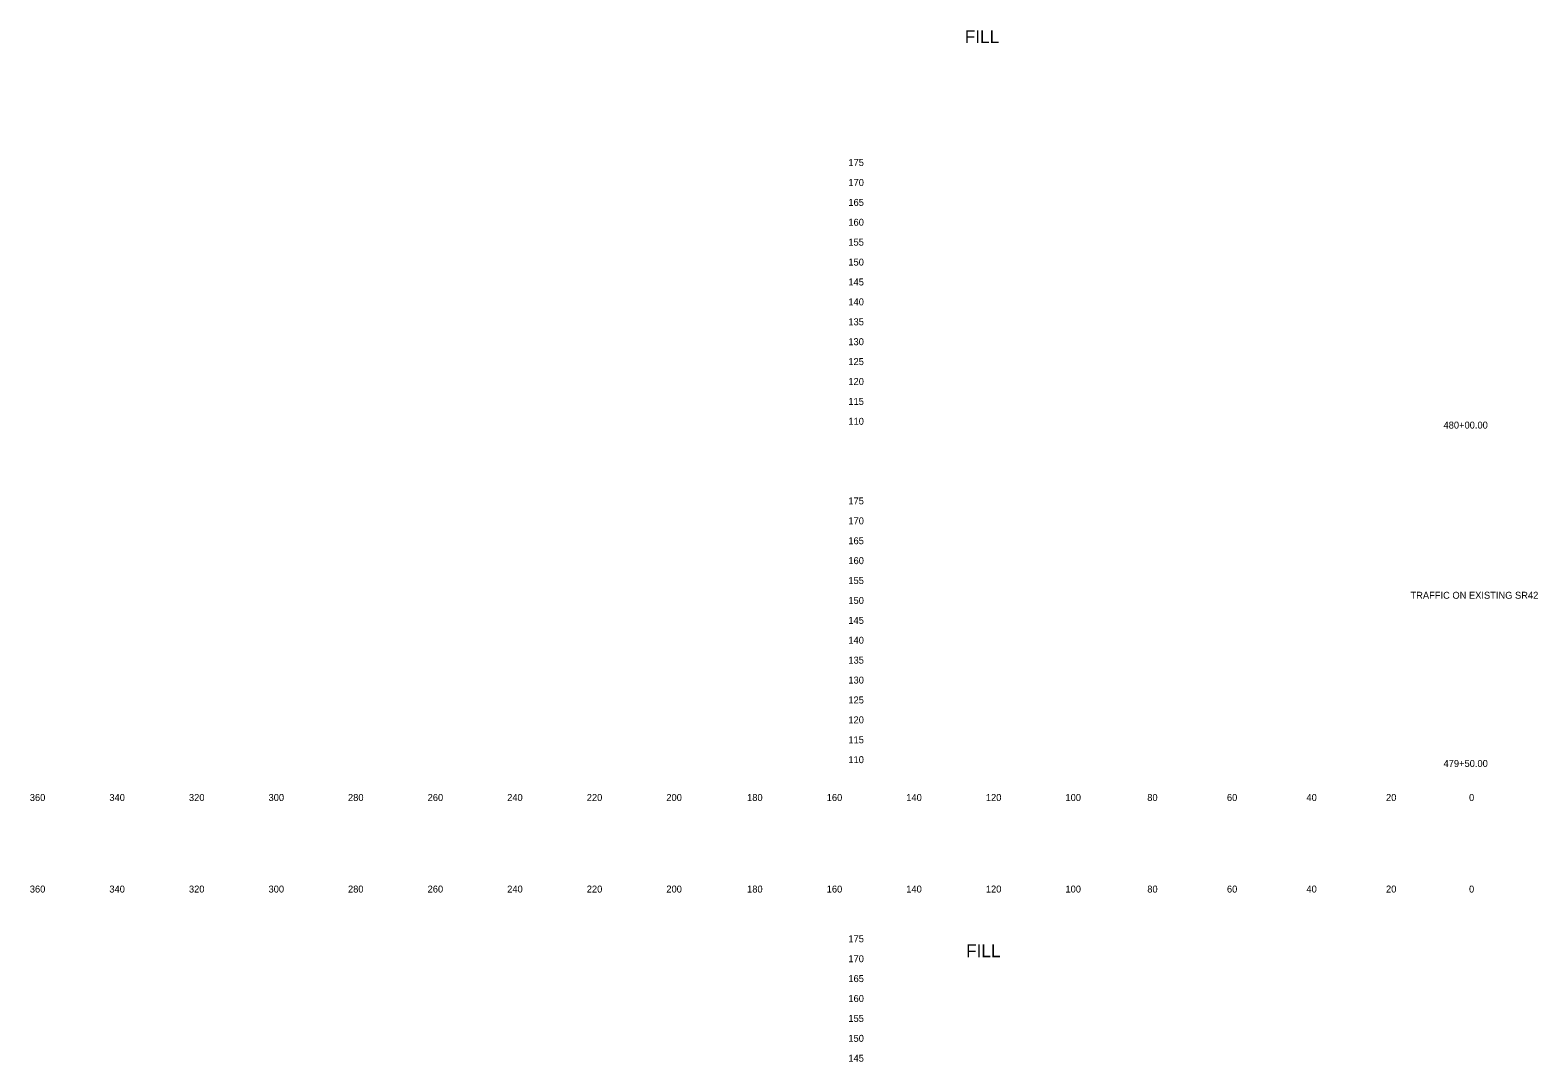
# Model space of a CAD drawing. Extents: x 21281 to 22024, y 6472 to 15198.
# Drawn here: x 21280.5 to 21659.4, y 11929.8 to 12189 of the extents above; entities that cross this region are included whole.
import ezdxf

# ---------------------------------------------------------------- set-up
doc = ezdxf.new("R2010")
doc.units = 0
for name, color, linetype in [('XS_SHEET_LABELS_ELEVATION', 7, 'Continuous'), ('XS_SHEET_LABELS_OFFSET', 7, 'Continuous'), ('XS_SHEET_LABELS_STATION', 7, 'Continuous')]:
    doc.layers.add(name, color=color, linetype=linetype)

msp = doc.modelspace()

# ---------------------------------------------------------------- texts
at = {"layer": 'XS_SHEET_LABELS_ELEVATION'}
for s, p in [('  175  ', (21484.84, 12154.84)), ('  170  ', (21484.84, 12149.84)), ('  165  ', (21484.84, 12144.84)), ('  160  ', (21484.84, 12139.84)), ('  155  ', (21484.84, 12134.84)), ('  150  ', (21484.84, 12129.84)), ('  145  ', (21484.84, 12124.84)), ('  140  ', (21484.84, 12119.84)), ('  135  ', (21484.84, 12114.84)), ('  130  ', (21484.84, 12109.84)), ('  125  ', (21484.84, 12104.84)), ('  120  ', (21484.84, 12099.84)), ('  115  ', (21484.84, 12094.84)), ('  110  ', (21484.84, 12089.84)), ('  175  ', (21484.84, 12069.84)), ('  170  ', (21484.84, 12064.84)), ('  165  ', (21484.84, 12059.84)), ('  160  ', (21484.84, 12054.84)), ('  155  ', (21484.84, 12049.84)), ('  150  ', (21484.84, 12044.84)), ('  145  ', (21484.84, 12039.84)), ('  140  ', (21484.84, 12034.84)), ('  135  ', (21484.84, 12029.84)), ('  130  ', (21484.84, 12024.84)), ('  125  ', (21484.84, 12019.84)), ('  120  ', (21484.84, 12014.84)), ('  115  ', (21484.84, 12009.84)), ('  110  ', (21484.84, 12004.84)), ('  175  ', (21484.84, 11959.84)), ('  170  ', (21484.84, 11954.84)), ('  165  ', (21484.84, 11949.84)), ('  160  ', (21484.84, 11944.84)), ('  155  ', (21484.84, 11939.84)), ('  150  ', (21484.84, 11934.84)), ('  145  ', (21484.84, 11929.84))]:
    msp.add_text(s, height=1.75, dxfattribs=at).set_placement(p)
at = {"layer": 'XS_SHEET_LABELS_OFFSET'}
for s, height, p in [('FILL', 3.222, (21515.4, 12185.75)), ('  360  ', 1.75, (21279.14, 11995.34)), ('  340  ', 1.75, (21299.13, 11995.34)), ('  320  ', 1.75, (21319.13, 11995.34)), ('  300  ', 1.75, (21339.13, 11995.34)), ('  280  ', 1.75, (21359.1, 11995.34)), ('  260  ', 1.75, (21379.11, 11995.34)), ('  240  ', 1.75, (21399.1, 11995.34)), ('  220  ', 1.75, (21419.1, 11995.34)), ('  200  ', 1.75, (21439.1, 11995.34)), ('  180  ', 1.75, (21459.39, 11995.34)), ('  160  ', 1.75, (21479.4, 11995.34)), ('  140  ', 1.75, (21499.39, 11995.34)), ('  120  ', 1.75, (21519.39, 11995.34)), ('  100  ', 1.75, (21539.39, 11995.34)), ('  80  ', 1.75, (21559.95, 11995.34)), ('  60  ', 1.75, (21579.97, 11995.34)), ('  40  ', 1.75, (21599.95, 11995.34)), ('  20  ', 1.75, (21619.95, 11995.34)), ('  0  ', 1.75, (21640.81, 11995.34)), ('  0  ', 1.75, (21640.81, 11995.34)), ('  360  ', 1.75, (21279.14, 11972.34)), ('  340  ', 1.75, (21299.13, 11972.34)), ('  320  ', 1.75, (21319.13, 11972.34)), ('  300  ', 1.75, (21339.13, 11972.34)), ('  280  ', 1.75, (21359.1, 11972.34)), ('  260  ', 1.75, (21379.11, 11972.34)), ('  240  ', 1.75, (21399.1, 11972.34)), ('  220  ', 1.75, (21419.1, 11972.34)), ('  200  ', 1.75, (21439.1, 11972.34)), ('  180  ', 1.75, (21459.39, 11972.34)), ('  160  ', 1.75, (21479.4, 11972.34)), ('  140  ', 1.75, (21499.39, 11972.34)), ('  120  ', 1.75, (21519.39, 11972.34)), ('  100  ', 1.75, (21539.39, 11972.34)), ('  80  ', 1.75, (21559.95, 11972.34)), ('  60  ', 1.75, (21579.97, 11972.34)), ('  40  ', 1.75, (21599.95, 11972.34)), ('  20  ', 1.75, (21619.95, 11972.34)), ('  0  ', 1.75, (21640.81, 11972.34)), ('  0  ', 1.75, (21640.81, 11972.34)), ('FILL', 3.222, (21515.74, 11956.09))]:
    msp.add_text(s, height=height, dxfattribs=at).set_placement(p)
at = {"layer": 'XS_SHEET_LABELS_STATION'}
for s, p in [('  480+00.00  ', (21634.4, 12088.89)), ('TRAFFIC ON EXISTING SR42', (21627.4, 12046.14)), ('  479+50.00  ', (21634.4, 12003.89))]:
    msp.add_text(s, height=1.75, dxfattribs=at).set_placement(p)

doc.saveas('drawing.dxf')
